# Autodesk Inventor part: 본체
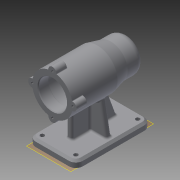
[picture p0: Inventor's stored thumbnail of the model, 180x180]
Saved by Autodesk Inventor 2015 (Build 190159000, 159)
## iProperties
Created: 2019-07
Part Number: 본체
Material: 일반
Document SubType Name: Modeling
Designer: now
Density: 1 g/cm^3
Appearance: 기본값
Author: now
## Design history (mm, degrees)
sketch "스케치1"
  geometry: C1 r 30 at (0, 0); 1 further point
  constraints: 1 centre point, 1 coincident
  dimensions: "d0" = 60 diameter of C1
extrude "돌출1" new body sketch "스케치1" distance "d1" = 16; taper "d2" = 0 deg
sketch "스케치2"
  geometry: C1 r 30 at (0, 0) reference; C2 r 30 at (0, 0)
  constraints: 1 centre point, 1 coincident
  dimensions: "d3" = 60 diameter of C2
extrude "돌출2" join sketch "스케치2" distance "d4" = 51; taper "d5" = 0 deg
sketch "스케치3"
  geometry: L1 (67, 30)-(67, -30) reference; L2 (67, -30)-(0, -30) reference; L3 (0, -30)-(0, 30) reference; L4 (0, 30)-(67, 30) reference; L5 (67, 30)-(67, -30) reference; L6 (67, -30)-(0, -30) reference; L7 (0, -30)-(0, 30) reference; L8 (0, 30)-(67, 30) reference; L9 (87, 25)-(112, 25); L10 (112, 25)-(112, 0); L11 (0, 0)-(112, 0); L12 (0, 30)-(0, -30) reference; L13 (67, 30)-(87, 25); L14 (67, 30)-(67, 0); L15 (67, -30)-(67, 30) reference
  constraints: 10 end point, 2 perpendicular, 1 horizontal, 1 midpoint
  dimensions: "d6" = 25 distance of L9.start L9.end; "d7" = 25 distance between parallel lines of L11 L9; "d8" = 45 distance between parallel lines of L10 L1
revolve "회전1" sketch "스케치3" stored, may be unused: angle "d9" = 90 deg
fillet "모깎기1" dims "d10" = 10
sketch "스케치4"
  geometry: L1 (112, 15)-(112, -15) reference; L2 (102, -25)-(87, -25) reference; L3 (87, -25)-(67, -30) reference; L4 (67, -30)-(0, -30) reference; L5 (0, -30)-(0, 30) reference; L6 (0, 30)-(67, 30) reference; L7 (67, 30)-(87, 25) reference; L8 (87, 25)-(102, 25) reference; L9 (0, 21)-(15, 21); L10 (15, 21)-(15, 0); L11 (15, 21)-(15, 24); L12 (15, 24)-(69, 24); L13 (69, 24)-(69, 0); L14 (69, 21)-(81, 21); L15 (81, 21)-(81, 0); L16 (81, 17.5)-(99, 17.5); L17 (99, 17.5)-(99, 0); L18 (103, 16)-(103, 0); L19 (99, 16)-(103, 16); L20 (106, 10.5)-(106, 0); L21 (0, 0)-(106, 0); L22 (106, 10.5)-(103, 10.5); A1 r 10 centre (102, 15) between (112, 15) and (102, 25) reference; A2 r 10 centre (102, -15) between (102, -25) and (112, -15) reference
  constraints: 28 end point, 7 perpendicular, 5 point on line, 4 vertical, 3 horizontal
  dimensions: "d11" = 15 distance between parallel lines of L10 L5; "d12" = 54 distance between parallel lines of L13 L10; "d13" = 12 distance between parallel lines of L15 L13; "d14" = 18 distance between parallel lines of L17 L15; "d15" = 4 distance between parallel lines of L18 L17; "d16" = 3 distance between parallel lines of L20 L18; "d17" = 21 distance between parallel lines of L21 L9; "d18" = 24 distance between parallel lines of L21 L12; "d19" = 21 distance between parallel lines of L21 L14; "d20" = 17.5 distance between parallel lines of L21 L16; "d22" = 16 distance between parallel lines of L21 L19; "d24" = 10.5 distance between parallel lines of L21 L22
revolve "회전2" sketch "스케치4" stored, may be unused: angle "d25" = 90 deg
node "작업 평면1"
sketch "스케치5"
  geometry: L1 (35, 0)-(-35, 0); L2 (-35, 0)-(-35, 112); L3 (-35, 112)-(35, 112); L4 (35, 112)-(35, 0); L5 (35, 0)-(-35, 112); L6 (-35, 0)-(35, 112); 4 further points
  constraints: 12 end point, 4 midpoint, 2 parallel, 2 vertical alignment, 1 horizontal, 1 perpendicular
  dimensions: "d27" = 112 distance of L1.end L2.end; "d28" = 56 distance of point (0, 56) point (0, 0); "d29" = 70 distance of L2.end L3.end
extrude "돌출3" join sketch "스케치5" distance "d30" = 10; taper "d31" = 0 deg
sketch "스케치6"
  geometry: L1 (-35, 0)-(35, 0) reference; L2 (35, 112)-(-35, 112) reference; L3 (-35, 112)-(-35, 0) reference; L4 (-28, 52)-(28, 52); L5 (28, 52)-(28, 60); L6 (28, 60)-(-28, 60); L7 (-28, 60)-(-28, 52); L8 (-28, 52)-(28, 60); L9 (28, 52)-(-28, 60); L10 (-4, 25)-(4, 25); L11 (4, 25)-(4, 92); L12 (4, 92)-(-4, 92); L13 (-4, 92)-(-4, 25); L14 (35, 0)-(35, 112) reference; 6 further points
  constraints: 20 end point, 4 midpoint, 4 parallel, 2 horizontal, 2 perpendicular, 2 vertical alignment
  dimensions: "d32" = 8 distance between parallel lines of L6 L4; "d33" = 56 distance from line of point (0, 56) L1; "d34" = 7 distance between parallel lines of L3 L7; "d35" = 56 distance of point (0, 0) point (0, 56); "d36" = 20 distance between parallel lines of L2 L12; "d37" = 8 distance between parallel lines of L11 L13; "d87" = 25 distance between parallel lines of L1 L10; "d88" = 31 distance between parallel lines of L14 L11; "d89" = 56 distance from line of point (0, 56) L2; "d90" = 35 distance from line of point (0, 56) L14
extrude "돌출4" join sketch "스케치6" stored distance "d38" = 10; taper "d39" = 0 deg
feature "면 기울기1" dims angle "d40" = 20 deg
feature "면 기울기2" dims angle "d41" = 10 deg
feature "면 기울기3" dims angle "d42" = 10 deg
fillet "모깎기2" dims "d43" = 10
sketch "스케치7"
  geometry: A1 r 10 centre (-25, 102) between (-25, 112) and (-35, 102) reference; A2 r 10 centre (-25, 10) between (-35, 10) and (-25, 0) reference; A3 r 10 centre (25, 10) between (25, 0) and (35, 10) reference; A4 r 10 centre (25, 102) between (35, 102) and (25, 112) reference; 1 further point
hole "구멍1" sketch "스케치7" at (25, 102), (25, 10), (-25, 102), (-25, 10) diameter "d44" = 6; stored, may be unused: countersink angle "d48" = 90 deg, drill point angle "d50" = 118 deg; dims "d45" = 6, "d46" = 4, "d47" = 2, "d49" = 8
fillet "모깎기3" dims "d51" = 0.3
fillet "모깎기4" dims "d52" = 3
chamfer "모따기1" distance "d53" = 1; stored, may be unused: second distance "d54" = 2, angle "d55" = 45 deg
fillet "모깎기5" dims "d56" = 3
sketch "스케치8"
  geometry: A1 r 30 centre (0, 0) between (0, 30) and (-5.97, 29.4) reference; A2 r 6 centre (0, 30) between (5.97, 29.4) and (-5.97, 29.4)
  constraints: 5 point on circle, 1 centre point, 1 vertical alignment
  dimensions: "d58" = 12 diameter of A2
extrude "돌출5" join sketch "스케치8" distance "d59" = 16; taper "d60" = 0 deg
fillet "모깎기6" dims "d61" = 1
fillet "모깎기7" dims "d62" = 1
sketch "스케치9"
  geometry: A1 r 6 centre (-30, 0) between (-30.171, 5.998) and (-30.171, -5.998) reference; A2 r 6 centre (0, -30) between (-5.998, -30.171) and (5.998, -30.171) reference; A3 r 6 centre (30, 0) between (30.171, -5.998) and (30.171, 5.998) reference; A4 r 6 centre (0, 30) between (5.998, 30.171) and (-5.998, 30.171) reference
hole "구멍2" sketch "스케치9" at (0, 30), (-30, 0), (0, -30), (30, 0) diameter "d66" = 3.242; stored, may be unused: countersink angle "d70" = 90 deg, drill point angle "d72" = 118 deg; dims "d67" = 8, "d68" = 4, "d69" = 2, "d71" = 11
fillet "모깎기9" dims "d75" = 3
fillet "모깎기11" dims "d77" = 3
fillet "모깎기12" dims "d78" = 3
node "작업 평면3"
sketch "스케치11"
  geometry: L1 (0, -5.998)-(0, 5.998) reference; 3 further points
  constraints: 1 horizontal alignment, 1 midpoint, 1 other
  dimensions: "d81" = 42 distance from line of L1 point (-42, 0)
feature "엠보싱2" sketch "스케치11" dims "d82" = 0.5, "d83" = 0
chamfer "모따기2" distance "d84" = 3; stored, may be unused: second distance "d85" = 2, angle "d86" = 45 deg
node "솔리드1"
pattern_circular "원형 패턴1" dims "d64" = 360 deg
node "절단 모서리 투영1"
node "절단 모서리 투영2"
node "절단 모서리 투영3"
